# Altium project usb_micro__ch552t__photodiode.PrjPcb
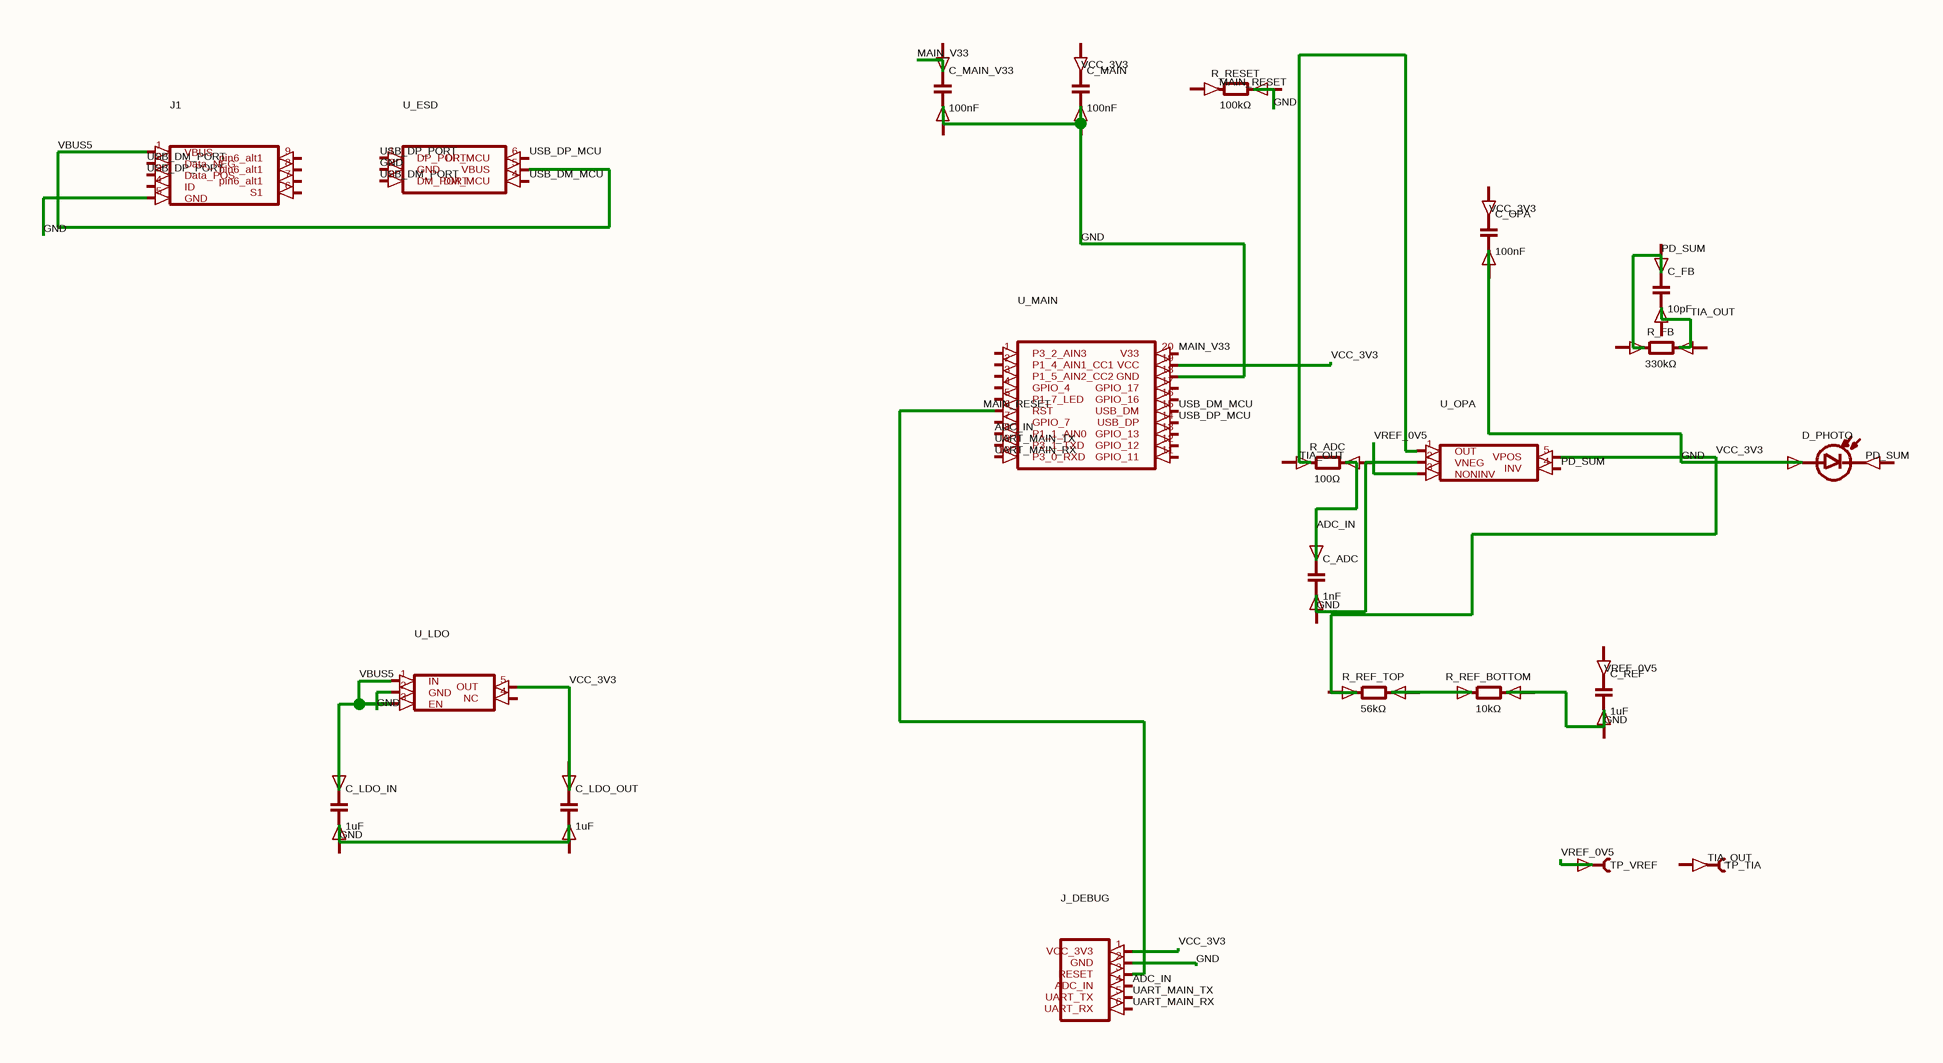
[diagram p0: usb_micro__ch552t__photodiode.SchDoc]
1 sheet, 22 parts. Net scope: global (net labels, ports and power ports of the same name join across sheets).
Board file: usb_micro__ch552t__photodiode.PcbDoc

## Sheet usb_micro__ch552t__photodiode.SchDoc
size 213 x 135 mm

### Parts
C_ADC  1nF
C_FB  10pF
C_LDO_IN  1uF
C_LDO_OUT  1uF
C_MAIN  100nF
C_MAIN_V33  100nF
C_OPA  100nF
C_REF  1uF
D_PHOTO  (no value)
J1  (no value)
J_DEBUG  (no value)
R_ADC  100Ω
R_FB  330kΩ
R_REF_BOTTOM  10kΩ
R_REF_TOP  56kΩ
R_RESET  100kΩ
TP_TIA  (no value)
TP_VREF  (no value)
U_ESD  (no value)
U_LDO  (no value)
U_MAIN  (no value)
U_OPA  (no value)

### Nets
ADC_IN: C_ADC.1(anode) J_DEBUG.4(ADC_IN) U_MAIN.8(P1_1_AIN0)
GND: C_LDO_OUT.1(anode) C_MAIN.2(cathode) C_OPA.2(cathode) D_PHOTO.1(anode) J1.5(GND) J_DEBUG.1(VCC_3V3) J_DEBUG.2(GND) J_DEBUG.3(RESET) R_ADC.2(cathode) R_REF_BOTTOM.2(cathode) TP_VREF.1(pin1) U_ESD.2(GND) U_LDO.2(GND) U_LDO.5(OUT) U_MAIN.6(RST) U_MAIN.18(GND) U_MAIN.19(VCC) U_OPA.2(VNEG) U_OPA.3(NONINV) U_OPA.5(VPOS)  [also labelled MAIN_RESET, VCC_3V3, VREF_0V5]
MAIN_V33: U_MAIN.20(V33)
PD_SUM: U_OPA.4(INV)
TIA_OUT: U_OPA.1(OUT)
UART_MAIN_RX: J_DEBUG.6(UART_RX) U_MAIN.10(P3_0_RXD)
UART_MAIN_TX: J_DEBUG.5(UART_TX) U_MAIN.9(P3_1_TXD)
USB_DM_MCU: U_ESD.4(DM_MCU) U_MAIN.15(USB_DM)
USB_DM_PORT: J1.2(Data_NEG) U_ESD.3(DM_PORT)
USB_DP_MCU: U_ESD.6(DP_MCU) U_MAIN.14(USB_DP)
USB_DP_PORT: J1.3(Data_POS) U_ESD.1(DP_PORT)
VBUS5: C_LDO_IN.1(anode) J1.1(VBUS) U_ESD.5(VBUS) U_LDO.1(IN) U_LDO.3(EN)
NetR_REF_BOTTOM_1: R_REF_BOTTOM.1(anode) R_REF_TOP.2(cathode)

Not connected (* = marked no-connect by the designer): C_ADC 2(cathode); C_FB 1(anode) 2(cathode); C_LDO_IN 2(cathode); C_LDO_OUT 2(cathode); C_MAIN 1(anode); C_MAIN_V33 1(anode) 2(cathode); C_OPA 1(anode); C_REF 1(anode) 2(cathode); D_PHOTO 2(cathode); J1 4(ID) 6(S1) 7(pin6_alt1) 8(pin6_alt1) 9(pin6_alt1); R_ADC 1(anode); R_FB 1(anode) 2(cathode); R_REF_TOP 1(anode); R_RESET 1(anode) 2(cathode); TP_TIA 1(pin1); U_LDO 4(NC); U_MAIN 1(P3_2_AIN3) 2(P1_4_AIN1_CC1) 3(P1_5_AIN2_CC2) 4(GPIO_4) 5(P1_7_LED) 7(GPIO_7) 11(GPIO_11) 12(GPIO_12) 13(GPIO_13) 16(GPIO_16) 17(GPIO_17)

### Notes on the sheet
- Labels drawn without touching a wire or pin: MAIN_RESET, PD_SUM, TIA_OUT, VCC_3V3, VREF_0V5

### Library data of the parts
C_ADC C_FB C_LDO_IN C_LDO_OUT C_MAIN C_MAIN_V33 C_OPA C_REF = capacitor_down
D_PHOTO = photodiode_horz
J1 = J1
J_DEBUG = J_DEBUG
R_ADC R_FB R_REF_BOTTOM R_REF_TOP R_RESET = boxresistor_right
TP_TIA TP_VREF = testpoint_right
U_ESD = U_ESD
U_LDO = U_LDO
U_MAIN = U_MAIN
U_OPA = U_OPA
